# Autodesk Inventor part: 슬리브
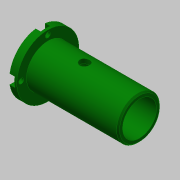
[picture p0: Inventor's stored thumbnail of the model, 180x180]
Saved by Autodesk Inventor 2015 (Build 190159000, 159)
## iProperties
Created: 2019-10
Part Number: 슬리브
Material: 알루미늄 6061
Document SubType Name: Modeling
Designer: mduedu
Density: 1 g/cm^3
Appearance: 진녹색
Author: mduedu
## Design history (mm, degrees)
sketch "스케치1"
  geometry: L1 (0, 0)-(5, 0); L2 (5, 0)-(5, 21); L3 (5, 21)-(0, 21); L4 (0, 21)-(0, 0); L5 (5, 0)-(67, 0); L6 (67, 0)-(67, 14.5); L7 (67, 14.5)-(5, 14.5); L8 (5, 14.5)-(5, 0)
  constraints: 16 end point, 4 parallel, 2 horizontal, 2 perpendicular
  dimensions: "d0" = 67 distance between parallel lines of L6 L4; "d2" = 62 distance of L6.end L7.end; "d3" = 42 diameter of L3 L1; "d4" = 29 diameter of L7 L5
revolve "회전1" sketch "스케치1" stored, may be unused: angle "d5" = 90 deg
hole "구멍1" diameter "d8" = 23; stored, may be unused: countersink angle "d12" = 90 deg, drill point angle "d14" = 118 deg; dims "d6" = 10, "d7" = 10, "d9" = 6, "d10" = 4, "d11" = 2, "d13" = 8
sketch "스케치2"
  geometry: L1 (-5, 21)-(-5, -21) reference; C1 r 3.3 at (-30, 0); 1 further point
  constraints: 1 centre point, 1 horizontal alignment
  dimensions: "d15" = 6.6 diameter of C1; "d16" = 25 distance from line of C1.centre L1
extrude "돌출1" cut sketch "스케치2" stored distance "d17" = 10; taper "d18" = 0 deg
chamfer "모따기1" distance "d19" = 1; stored, may be unused: second distance "d20" = 2, angle "d21" = 45 deg
sketch "스케치3" dims "d22" = 36
  geometry: 6 further points
  constraints: 2 vertical alignment, 1 coincident, 7 other
  dimensions: "d25" = 360 deg dimension on point (0, 0) point (0, 18) (derived)
sketch "스케치4"
  geometry: 4 further points
  constraints: 4 other
hole "구멍2" sketch "스케치4" at (-18, 0), (0, -18), (18, 0), (0, 18) diameter "d27" = 3.4; stored, may be unused: countersink angle "d31" = 90 deg, drill point angle "d33" = 0 deg; dims "d28" = 6, "d29" = 6.5, "d30" = 3.4, "d32" = 8
sketch "스케치5"
  geometry: L1 (-21.25, 20.747)-(-21.25, 18); L2 (-14.75, 18)-(-14.75, 20.747); A1 r 3.25 centre (-18, 18) between (-19.349, 20.957) and (-16.651, 20.957) reference; A2 r 21 centre (-18, 0) between (-19.349, 20.957) and (-38.957, 1.349) reference; A3 r 21 centre (-18, 0) between (2.957, 1.349) and (-16.651, 20.957) reference; A4 r 21 centre (-18, 0) between (-14.75, 20.747) and (-21.25, 20.747); A5 r 3.25 centre (-18, 18) between (-21.25, 18) and (-14.75, 18); 1 further point
  constraints: 8 point on circle, 4 end point, 2 centre point, 2 coincident, 2 tangent, 1 parallel, 1 vertical
extrude "돌출2" cut sketch "스케치5" stored distance "d34" = 10; taper "d35" = 0 deg
node "솔리드1"
pattern_circular "원형 패턴1" dims angle "d37" = 360 deg
